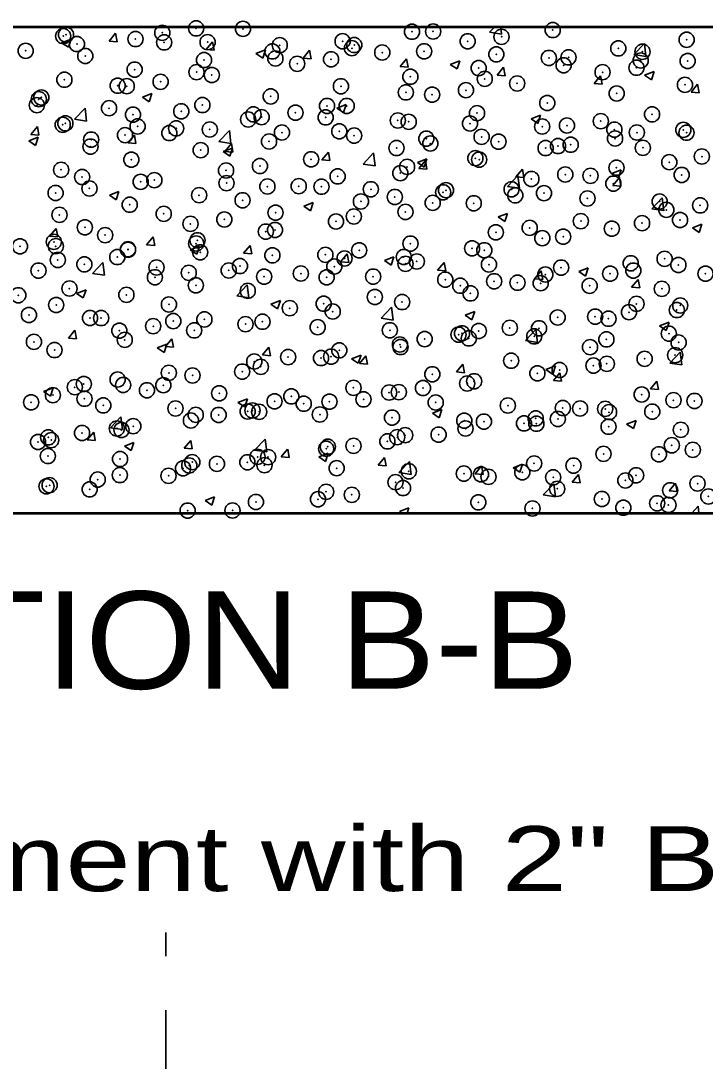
# Model space of a CAD drawing. Extents: x 14 to 49.3, y 28 to 50.
# Drawn here: x 21.16 to 22.425, y 46.258 to 48.18 of the extents above; entities that cross this region are included whole.
import ezdxf

# ---------------------------------------------------------------- set-up
doc = ezdxf.new("R2010")
doc.units = 0
doc.header["$LTSCALE"] = 0.056
doc.header["$PDMODE"] = 32
doc.header["$PDSIZE"] = 0.028
doc.linetypes.add('LONG_DASH_SHORT_DASH', pattern=[9.9, 6, -1.2, 1.5, -1.2])
for name, color, linetype, lineweight in [('1', 7, 'Continuous', 35), ('3', 7, 'Continuous', 13), ('7', 7, 'LONG_DASH_SHORT_DASH', 35)]:
    doc.layers.add(name, color=color, linetype=linetype, lineweight=lineweight)

msp = doc.modelspace()

# ---------------------------------------------------------------- linework, layer by layer
at = {"layer": '1'}
for p, q in [((22.02617, 48.15917), (22.03525, 48.16867)), ((22.04842, 48.15575), (22.04692, 48.16867)), ((21.23508, 48.13975), (21.25258, 48.1465)), ((21.2475, 48.13142), (21.25258, 48.1465)), ((21.32283, 48.14275), (21.33492, 48.15708)), ((21.32283, 48.14275), (21.33775, 48.14142)), ((21.33775, 48.14142), (21.33492, 48.15708)), ((21.50217, 48.127), (21.51417, 48.14142)), ((21.51708, 48.12575), (21.51425, 48.14142)), ((22.02617, 48.15917), (22.04833, 48.15575)), ((21.23508, 48.13975), (21.2475, 48.13142)), ((21.50217, 48.127), (21.51708, 48.12575)), ((21.59433, 48.11975), (21.61183, 48.1265)), ((21.60683, 48.11133), (21.61183, 48.1265)), ((21.68142, 48.11133), (21.6935, 48.12567)), ((21.69642, 48.11), (21.6935, 48.12567)), ((22.29292, 48.11783), (22.31242, 48.13808)), ((22.31517, 48.11433), (22.31242, 48.13808)), ((21.59433, 48.11975), (21.60675, 48.11142)), ((21.68142, 48.11133), (21.69642, 48.11)), ((21.86075, 48.09567), (21.87283, 48.11)), ((21.87575, 48.09433), (21.87283, 48.11)), ((21.95367, 48.09975), (21.97117, 48.1065)), ((21.96608, 48.09133), (21.97117, 48.10642)), ((22.29292, 48.11783), (22.31517, 48.11433)), ((21.86075, 48.09567), (21.87575, 48.09433)), ((21.95367, 48.09975), (21.96608, 48.09133)), ((22.04008, 48.08), (22.05217, 48.09433)), ((22.05508, 48.07867), (22.05217, 48.09433)), ((22.31292, 48.07975), (22.33042, 48.08642)), ((22.32533, 48.07133), (22.33042, 48.08642)), ((22.04008, 48.08), (22.055, 48.07867)), ((22.21942, 48.06425), (22.23142, 48.07867)), ((22.21942, 48.06425), (22.23433, 48.063)), ((22.23433, 48.063), (22.2315, 48.07867)), ((22.31292, 48.07975), (22.32533, 48.07133)), ((21.38433, 48.03917), (21.40183, 48.04583)), ((21.39675, 48.03075), (21.40183, 48.04583)), ((22.39875, 48.04858), (22.41075, 48.06292)), ((22.39875, 48.04858), (22.41367, 48.04725)), ((22.41367, 48.04725), (22.41075, 48.06292)), ((21.38433, 48.03917), (21.39675, 48.03075)), ((21.74358, 48.01908), (21.76108, 48.02583)), ((21.756, 48.01075), (21.76108, 48.02583)), ((21.25883, 47.99842), (21.27833, 48.01875)), ((21.28108, 47.995), (21.27833, 48.01875)), ((21.74358, 48.01908), (21.756, 48.01075)), ((22.10283, 47.99908), (22.12033, 48.00583)), ((22.11533, 47.99067), (22.12042, 48.00583)), ((21.25883, 47.99842), (21.28108, 47.995)), ((22.10283, 47.99908), (22.11533, 47.99067)), ((21.17817, 47.97033), (21.19025, 47.98475)), ((21.17817, 47.97033), (21.19317, 47.96908)), ((21.19317, 47.96908), (21.19025, 47.98475)), ((21.3575, 47.95467), (21.36958, 47.969)), ((21.3725, 47.95333), (21.36958, 47.969)), ((21.52567, 47.95708), (21.54517, 47.97733)), ((21.54792, 47.95358), (21.54517, 47.97733)), ((21.17425, 47.9585), (21.19175, 47.96525)), ((21.17425, 47.9585), (21.18667, 47.95008)), ((21.18667, 47.95008), (21.19175, 47.96525)), ((21.3575, 47.95467), (21.37242, 47.95333)), ((21.52567, 47.95708), (21.54792, 47.95358)), ((21.52567, 47.95708), (21.54792, 47.95358)), ((21.53683, 47.939), (21.54892, 47.95333)), ((21.55175, 47.93767), (21.54892, 47.95333)), ((21.5335, 47.9385), (21.551, 47.94517)), ((21.5335, 47.9385), (21.546, 47.93008)), ((21.53683, 47.939), (21.55175, 47.93767)), ((21.546, 47.93008), (21.55108, 47.94517)), ((21.71617, 47.92333), (21.72817, 47.93767)), ((21.73108, 47.922), (21.72825, 47.93767)), ((21.7925, 47.91567), (21.81192, 47.936)), ((21.81475, 47.91225), (21.81192, 47.93592)), ((21.71617, 47.92333), (21.73108, 47.922)), ((21.7925, 47.91567), (21.81467, 47.91225)), ((21.89283, 47.91842), (21.91033, 47.92517)), ((21.89283, 47.91842), (21.90525, 47.91008)), ((21.8955, 47.90758), (21.9075, 47.922)), ((21.90525, 47.91008), (21.91033, 47.92517)), ((21.91042, 47.90633), (21.9075, 47.922)), ((21.8955, 47.90758), (21.91042, 47.90633)), ((22.05925, 47.87425), (22.07875, 47.89458)), ((22.07475, 47.89192), (22.08683, 47.90625)), ((22.07475, 47.89192), (22.08975, 47.89058)), ((22.0815, 47.87083), (22.07875, 47.89458)), ((22.08975, 47.89058), (22.08683, 47.90625)), ((22.25208, 47.89842), (22.26958, 47.90517)), ((22.25208, 47.89842), (22.2645, 47.89008)), ((22.25408, 47.87625), (22.26617, 47.89058)), ((22.2645, 47.89), (22.26958, 47.90517)), ((22.26908, 47.87492), (22.26617, 47.89058)), ((22.05925, 47.87425), (22.0815, 47.87083)), ((22.25408, 47.87625), (22.269, 47.87492)), ((21.3235, 47.85783), (21.341, 47.86458)), ((21.3235, 47.85783), (21.33592, 47.84942)), ((21.33592, 47.84942), (21.341, 47.86458)), ((22.32608, 47.83292), (22.34558, 47.85317)), ((22.34833, 47.82942), (22.34558, 47.85317)), ((21.68275, 47.83783), (21.70025, 47.8445)), ((21.68275, 47.83783), (21.69517, 47.82942)), ((21.69517, 47.82942), (21.70025, 47.8445)), ((22.32608, 47.83292), (22.34833, 47.8295)), ((22.042, 47.81783), (22.0595, 47.8245)), ((22.042, 47.81783), (22.0545, 47.80942)), ((22.0545, 47.80942), (22.05958, 47.8245)), ((21.21292, 47.78233), (21.22492, 47.79667)), ((21.22783, 47.781), (21.22492, 47.79667)), ((22.40133, 47.79775), (22.41883, 47.8045)), ((22.40133, 47.79775), (22.41375, 47.78942)), ((22.41375, 47.78942), (22.41883, 47.8045)), ((21.21292, 47.78233), (21.22783, 47.781)), ((21.39217, 47.76658), (21.40425, 47.781)), ((21.40717, 47.76533), (21.40425, 47.781)), ((21.39217, 47.76658), (21.40717, 47.76533)), ((21.47267, 47.75717), (21.49017, 47.76392)), ((21.47267, 47.75717), (21.48517, 47.74883)), ((21.48517, 47.74883), (21.49025, 47.76392)), ((21.5715, 47.75092), (21.58358, 47.76533)), ((21.5865, 47.74958), (21.58358, 47.76533)), ((21.5715, 47.75092), (21.5865, 47.74967)), ((21.75083, 47.73525), (21.76292, 47.74958)), ((21.76575, 47.73392), (21.76292, 47.74958)), ((21.832, 47.73717), (21.8495, 47.74392)), ((21.832, 47.73717), (21.84442, 47.72875)), ((21.84442, 47.72875), (21.8495, 47.74392)), ((21.292, 47.7135), (21.3115, 47.73383)), ((21.31425, 47.71008), (21.3115, 47.73383)), ((21.75083, 47.73525), (21.76575, 47.73392)), ((21.93017, 47.71958), (21.94217, 47.73392)), ((21.93017, 47.71958), (21.94508, 47.71825)), ((21.94508, 47.71825), (21.94225, 47.73392)), ((22.1095, 47.70383), (22.1215, 47.71825)), ((22.12442, 47.70258), (22.1215, 47.71825)), ((22.19125, 47.71717), (22.20875, 47.72383)), ((22.20375, 47.70875), (22.20875, 47.72383)), ((21.292, 47.7135), (21.31425, 47.71008)), ((22.1095, 47.70383), (22.12442, 47.70258)), ((22.19125, 47.71717), (22.20367, 47.70875)), ((22.28875, 47.68817), (22.30083, 47.70258)), ((22.30375, 47.68683), (22.30083, 47.7025)), ((21.26267, 47.67658), (21.28017, 47.68325)), ((21.27508, 47.66817), (21.28017, 47.68325)), ((21.55883, 47.67217), (21.57825, 47.69242)), ((21.58108, 47.66867), (21.57825, 47.69242)), ((22.28875, 47.68817), (22.30375, 47.68683)), ((21.26267, 47.67658), (21.27508, 47.66817)), ((21.55883, 47.67217), (21.581, 47.66867)), ((21.62192, 47.6565), (21.63942, 47.66325)), ((21.63433, 47.64817), (21.63942, 47.66325)), ((21.62192, 47.6565), (21.63433, 47.64817)), ((21.82558, 47.63075), (21.84508, 47.65108)), ((21.84783, 47.62733), (21.84508, 47.65108)), ((21.98117, 47.6365), (21.99875, 47.64325)), ((21.99367, 47.62808), (21.99875, 47.64325)), ((21.82558, 47.63075), (21.84783, 47.62733)), ((21.98117, 47.6365), (21.99367, 47.62808)), ((22.3405, 47.6165), (22.358, 47.62325)), ((22.35292, 47.60808), (22.358, 47.62317)), ((21.24758, 47.59425), (21.25967, 47.60867)), ((21.2625, 47.59292), (21.25967, 47.60858)), ((22.09242, 47.58942), (22.11192, 47.60967)), ((22.11467, 47.58592), (22.11192, 47.60967)), ((22.3405, 47.6165), (22.35292, 47.60808)), ((21.24758, 47.59425), (21.2625, 47.59292)), ((21.42692, 47.57858), (21.43892, 47.59292)), ((21.44183, 47.57725), (21.43892, 47.59292)), ((21.44183, 47.57725), (21.43892, 47.59292)), ((22.09242, 47.58942), (22.11467, 47.58592)), ((21.41183, 47.57592), (21.42933, 47.58258)), ((21.41183, 47.57592), (21.42433, 47.5675)), ((21.42433, 47.5675), (21.42942, 47.58258)), ((21.42692, 47.57858), (21.44183, 47.57725)), ((21.60617, 47.56292), (21.61825, 47.57725)), ((21.62117, 47.56158), (21.61825, 47.57725)), ((22.35925, 47.548), (22.37867, 47.56833)), ((22.3815, 47.54458), (22.37875, 47.56825)), ((21.60617, 47.56292), (21.62117, 47.56158)), ((21.77117, 47.55592), (21.78867, 47.56258)), ((21.77117, 47.55592), (21.78358, 47.5475)), ((21.78358, 47.5475), (21.78867, 47.56258)), ((21.7855, 47.54717), (21.79758, 47.56158)), ((21.7855, 47.54717), (21.8005, 47.54592)), ((21.8005, 47.54592), (21.79758, 47.56158)), ((21.96483, 47.5315), (21.97692, 47.54583)), ((21.97983, 47.53017), (21.97692, 47.54583)), ((22.35925, 47.548), (22.3815, 47.54458)), ((21.96483, 47.5315), (21.97975, 47.53017)), ((22.13042, 47.53583), (22.14792, 47.54258)), ((22.13042, 47.53583), (22.14283, 47.5275)), ((22.14292, 47.5275), (22.14792, 47.54258)), ((22.14417, 47.51583), (22.15617, 47.53017)), ((22.15908, 47.5145), (22.15625, 47.53017)), ((22.14417, 47.51583), (22.15908, 47.5145)), ((22.3235, 47.50017), (22.3355, 47.5145)), ((22.33842, 47.49883), (22.3355, 47.5145)), ((21.20183, 47.49525), (21.21933, 47.502)), ((21.20183, 47.49525), (21.21425, 47.48692)), ((21.21425, 47.48692), (21.21933, 47.502)), ((22.3235, 47.50017), (22.33842, 47.49883)), ((21.56108, 47.47525), (21.57858, 47.482)), ((21.56108, 47.47525), (21.5735, 47.46683)), ((21.57358, 47.46683), (21.57858, 47.482)), ((21.32517, 47.42858), (21.34458, 47.44892)), ((21.34742, 47.42517), (21.34458, 47.44892)), ((21.92042, 47.45525), (21.93792, 47.46192)), ((21.92042, 47.45525), (21.93283, 47.44683)), ((21.93283, 47.44683), (21.93792, 47.46192)), ((22.27967, 47.43517), (22.29717, 47.44192)), ((22.27967, 47.43517), (22.29208, 47.42683)), ((22.29208, 47.42683), (22.29717, 47.44192)), ((21.28225, 47.40625), (21.29433, 47.42058)), ((21.29725, 47.40492), (21.29433, 47.42058)), ((21.32517, 47.42858), (21.34733, 47.42517)), ((21.28225, 47.40625), (21.29717, 47.40492)), ((21.351, 47.39458), (21.36858, 47.40133)), ((21.351, 47.39458), (21.3635, 47.38625)), ((21.3635, 47.38625), (21.36858, 47.40133)), ((21.46158, 47.3905), (21.47367, 47.40492)), ((21.46158, 47.3905), (21.4765, 47.38925)), ((21.4765, 47.38925), (21.47367, 47.40492)), ((21.59192, 47.38725), (21.61142, 47.4075)), ((21.61417, 47.38375), (21.61142, 47.4075)), ((21.59192, 47.38725), (21.61417, 47.38375)), ((21.64092, 47.37483), (21.65292, 47.38917)), ((21.64092, 47.37483), (21.65583, 47.3735)), ((21.65583, 47.3735), (21.653, 47.38917)), ((21.71033, 47.37458), (21.72783, 47.38133)), ((21.71033, 47.37458), (21.72275, 47.36617)), ((21.71033, 47.37458), (21.72275, 47.36617)), ((21.72275, 47.36617), (21.72783, 47.38133)), ((21.82017, 47.35917), (21.83225, 47.3735)), ((21.83517, 47.35783), (21.83225, 47.3735)), ((21.82017, 47.35917), (21.83517, 47.35783)), ((21.85875, 47.34583), (21.87825, 47.36617)), ((21.881, 47.34242), (21.87825, 47.36617)), ((21.9995, 47.3435), (22.01158, 47.35783)), ((22.0145, 47.34217), (22.01158, 47.35783)), ((22.06958, 47.35458), (22.08708, 47.36125)), ((22.06958, 47.35458), (22.082, 47.34617)), ((22.08208, 47.34617), (22.08708, 47.36125)), ((21.85875, 47.34583), (21.881, 47.34242)), ((21.9995, 47.3435), (22.0145, 47.34217)), ((22.17883, 47.32775), (22.19092, 47.34217)), ((22.19383, 47.3265), (22.19092, 47.34217)), ((22.12558, 47.3045), (22.145, 47.32475)), ((22.14783, 47.301), (22.14508, 47.32475)), ((22.17883, 47.32775), (22.19375, 47.3265)), ((22.35817, 47.31208), (22.37017, 47.32642)), ((22.37308, 47.31075), (22.37025, 47.32642)), ((21.50025, 47.294), (21.51775, 47.30067)), ((21.51275, 47.28558), (21.51775, 47.30067)), ((22.12558, 47.3045), (22.14783, 47.301)), ((22.35817, 47.31208), (22.37308, 47.31075)), ((21.50025, 47.294), (21.51267, 47.28558)), ((21.85958, 47.27392), (21.87708, 47.28067)), ((21.87383, 47.271), (21.87708, 47.28067)), ((22.4, 47.271), (22.41183, 47.28342)), ((22.41333, 47.271), (22.41183, 47.28342)), ((21.85958, 47.27392), (21.86383, 47.271))]:
    msp.add_line(p, q, dxfattribs=at)
at = {"layer": '1', "lineweight": 53}
for points in [[(22.63958, 47.92558), (22.63958, 48.05642), (22.63067, 48.12192), (22.57725, 48.16867), (20.43842, 48.16867), (20.39383, 48.11258), (20.38492, 48.02842)], [(18.87883, 47.271), (23.89617, 47.271), (23.90508, 47.29908), (23.88725, 47.34583), (23.86942, 47.39258), (23.89617, 47.43933), (23.92292, 47.47675), (23.914, 47.51417), (23.87833, 47.57958), (23.8605, 47.63567), (23.89617, 47.66375), (23.914, 47.77592), (23.914, 47.79467)]]:
    msp.add_lwpolyline(points, dxfattribs=at)
at = {"layer": '1'}
for p in [(21.48375, 48.16617), (21.57033, 48.16525), (21.238, 48.152), (21.24317, 48.15458), (21.3715, 48.14642), (21.42117, 48.158), (21.88283, 48.16), (21.92183, 48.16042), (22.04833, 48.15058), (22.143, 48.16308), (21.26333, 48.13717), (21.42458, 48.14025), (21.50492, 48.14075), (21.63833, 48.13508), (21.7545, 48.14242), (21.77183, 48.1295), (21.77608, 48.13542), (21.98575, 48.14233), (22.26425, 48.12917), (22.39058, 48.14517), (21.16858, 48.12475), (21.27875, 48.11525), (21.49833, 48.10767), (21.62467, 48.12367), (21.63025, 48.11042), (21.73317, 48.10908), (21.82783, 48.12158), (21.90525, 48.12383), (22.03875, 48.11817), (22.13592, 48.11158), (22.17217, 48.11258), (22.30567, 48.10692), (22.30892, 48.123), (21.37, 48.09008), (21.67058, 48.10083), (22.00608, 48.09283), (22.16317, 48.098), (22.29775, 48.0935), (22.39242, 48.10592), (21.24017, 48.07133), (21.4845, 48.08533), (21.51267, 48.08008), (21.87983, 48.07683), (22.01733, 48.07292), (22.23517, 48.08525), (21.33867, 48.06033), (21.35542, 48.05933), (21.418, 48.06758), (21.75142, 48.05925), (21.98258, 48.052), (22.07725, 48.06442), (22.3875, 48.06192), (21.19283, 48.03533), (21.1975, 48.03858), (21.62158, 48.0405), (21.8715, 48.04792), (21.92, 48.04375), (22.26125, 48.04592), (21.18933, 48.02425), (21.32275, 48.01867), (21.45625, 48.013), (21.49533, 48.0245), (21.72575, 48.02292), (21.76208, 48.02292), (22.13292, 48.02833), (21.367, 48.00683), (21.57992, 47.99783), (21.58967, 48.00733), (21.60483, 48.00225), (21.66742, 48.0105), (21.72317, 48.00175), (21.85658, 47.99608), (21.87675, 47.99358), (22.00308, 48.00958), (22.23192, 47.99483), (22.32667, 48.00733), (21.23708, 47.98808), (21.242, 47.99075), (21.3755, 47.98508), (21.43417, 47.97283), (21.44692, 47.9815), (21.50892, 47.97942), (21.64242, 47.97383), (21.74842, 47.976), (21.99008, 47.99042), (22.1235, 47.98483), (22.16933, 47.98667), (22.257, 47.97917), (22.29858, 47.97383), (22.3845, 47.97875), (22.39042, 47.9735), (21.28967, 47.96075), (21.35225, 47.969), (21.61858, 47.95725), (21.77583, 47.96817), (21.90933, 47.9625), (21.91675, 47.95342), (22.0115, 47.96583), (22.04275, 47.95692), (22.25825, 47.96275), (21.28833, 47.94783), (21.49225, 47.94125), (21.85417, 47.94517), (22.12983, 47.94508), (22.15283, 47.94883), (22.17625, 47.95125), (22.30967, 47.94558), (21.36392, 47.92367), (21.69633, 47.92433), (22, 47.92633), (22.007, 47.92375), (22.3585, 47.91892), (22.41875, 47.9295), (21.23408, 47.90492), (21.53908, 47.90367), (21.60167, 47.91192), (21.86125, 47.89875), (21.87375, 47.91033), (22.16617, 47.89625), (22.26083, 47.90875), (22.38142, 47.8955), (21.273, 47.89158), (21.38117, 47.88283), (21.4065, 47.88592), (21.53992, 47.88033), (21.74533, 47.89275), (22.10358, 47.888), (22.21275, 47.89392), (22.25517, 47.8795), (21.22392, 47.86217), (21.2865, 47.87042), (21.48925, 47.858), (21.6155, 47.874), (21.67342, 47.87467), (21.71542, 47.87375), (21.80683, 47.869), (21.94033, 47.86342), (21.94567, 47.86725), (22.06692, 47.86892), (22.07375, 47.85775), (22.12683, 47.86192), (21.36092, 47.84042), (21.56958, 47.84867), (21.78842, 47.8465), (21.851, 47.85475), (21.92108, 47.84383), (21.997, 47.84317), (22.20725, 47.85208), (22.34067, 47.8465), (22.41558, 47.83917), (21.231, 47.82167), (21.42383, 47.82367), (21.63058, 47.82575), (21.77533, 47.81883), (21.87067, 47.82717), (22.353, 47.83092), (21.47325, 47.80508), (21.53583, 47.81325), (21.74233, 47.8095), (22.19508, 47.81017), (22.30817, 47.80642), (22.37842, 47.81225), (21.278, 47.79867), (21.31542, 47.78425), (21.6125, 47.79083), (21.6295, 47.79383), (22.03783, 47.78942), (22.10042, 47.79767), (22.16242, 47.78142), (22.25217, 47.79625), (21.15808, 47.76358), (21.22075, 47.77183), (21.22433, 47.76383), (21.48375, 47.76875), (21.48617, 47.77475), (21.87992, 47.76867), (22.12375, 47.77867), (21.33792, 47.74375), (21.35783, 47.75817), (21.35783, 47.75717), (21.49125, 47.75258), (21.62475, 47.74692), (21.72267, 47.74792), (21.78525, 47.75617), (21.86767, 47.74392), (21.99392, 47.75992), (22.01658, 47.75633), (21.228, 47.73842), (21.27708, 47.73025), (21.4105, 47.72458), (21.56475, 47.72717), (21.73925, 47.72633), (21.75817, 47.74125), (21.87083, 47.73133), (21.89167, 47.73567), (22.02508, 47.73), (22.15858, 47.72433), (22.28725, 47.73233), (22.34983, 47.74058), (22.37533, 47.72908), (21.19217, 47.71875), (21.4075, 47.70642), (21.47008, 47.71467), (21.544, 47.719), (21.60942, 47.70758), (21.67742, 47.71333), (21.725, 47.70633), (21.81092, 47.70767), (22.12933, 47.7115), (22.24908, 47.71308), (22.292, 47.71875), (22.42542, 47.71308), (21.24958, 47.68567), (21.48317, 47.69158), (21.94433, 47.70208), (21.97208, 47.69083), (22.03467, 47.69908), (22.07783, 47.69642), (22.12075, 47.69542), (22.21125, 47.69075), (22.34475, 47.68517), (21.15492, 47.67317), (21.35483, 47.674), (21.57917, 47.68133), (21.81417, 47.67), (21.99092, 47.67667), (21.225, 47.65525), (21.43342, 47.65625), (21.65692, 47.64933), (21.7195, 47.65758), (21.86458, 47.66067), (22.29783, 47.65725), (22.37233, 47.64583), (22.37875, 47.65442), (21.17458, 47.63675), (21.28758, 47.63125), (21.30808, 47.63108), (21.499, 47.62858), (21.73625, 47.64308), (22.15208, 47.63225), (22.22142, 47.63375), (22.24608, 47.62983), (22.284, 47.64192), (21.34175, 47.60783), (21.40433, 47.61608), (21.4415, 47.6255), (21.48017, 47.60833), (21.575, 47.61983), (21.60642, 47.62433), (21.70842, 47.61417), (21.84192, 47.60858), (22.00625, 47.60717), (22.06358, 47.61292), (22.11767, 47.61225), (21.35175, 47.59075), (21.90625, 47.59225), (21.96883, 47.6005), (21.97533, 47.60292), (21.98783, 47.5935), (22.10883, 47.59725), (22.24225, 47.59167), (22.35775, 47.60233), (21.18383, 47.58708), (21.22192, 47.572), (21.74842, 47.57142), (21.8605, 47.58217), (21.86158, 47.5775), (22.212, 47.57733), (22.37575, 47.586), (21.59117, 47.55075), (21.65375, 47.559), (21.71467, 47.55717), (21.73325, 47.55983), (22.06617, 47.55233), (22.31292, 47.55583), (22.36925, 47.56258), (21.56892, 47.53217), (21.60333, 47.54108), (22.15567, 47.53508), (22.21825, 47.54333), (22.243, 47.54658), (21.33858, 47.5175), (21.43325, 47.52992), (21.47708, 47.52508), (21.92042, 47.52725), (21.99775, 47.51433), (22.11467, 47.529), (21.25942, 47.50333), (21.276, 47.50925), (21.34875, 47.5075), (21.39283, 47.49775), (21.42308, 47.50708), (21.52633, 47.49208), (21.77458, 47.50225), (21.8405, 47.49358), (21.8585, 47.49425), (21.90308, 47.50183), (21.98483, 47.51025), (21.17867, 47.47542), (21.21892, 47.48875), (21.27725, 47.48208), (21.62875, 47.47725), (21.65975, 47.48642), (21.68267, 47.47283), (21.73017, 47.47667), (21.79325, 47.48083), (21.92667, 47.47517), (22.30742, 47.48983), (22.36625, 47.47942), (22.40508, 47.478), (21.31208, 47.46975), (21.44558, 47.46417), (21.579, 47.4585), (21.58792, 47.46033), (21.60033, 47.45792), (22.06008, 47.4695), (22.16167, 47.46483), (22.19358, 47.46392), (22.24, 47.46342), (22.24717, 47.45725), (22.327, 47.45825), (21.47408, 47.44192), (21.483, 47.45225), (21.52533, 47.45217), (21.7125, 47.45283), (21.84592, 47.44725), (21.97942, 47.44158), (22.01583, 47.43983), (22.08992, 47.4365), (22.11158, 47.44575), (22.11283, 47.43592), (22.1525, 47.44475), (21.27283, 47.41883), (21.33717, 47.42717), (21.34567, 47.42433), (21.3675, 47.43133), (21.932, 47.41575), (21.98175, 47.427), (22.24625, 47.43033), (22.37975, 47.42467), (21.19142, 47.40217), (21.21025, 47.41067), (21.21583, 47.40558), (21.83733, 47.40325), (21.8555, 47.411), (21.87008, 47.41475), (22.36317, 47.39617), (21.72425, 47.38975), (21.72717, 47.39342), (21.77475, 47.395), (22.23692, 47.38017), (22.33933, 47.37942), (22.40192, 47.38767), (21.20967, 47.37625), (21.34308, 47.37067), (21.471, 47.35867), (21.47658, 47.365), (21.52217, 47.36175), (21.5785, 47.36475), (21.59725, 47.37467), (21.61, 47.35933), (21.61683, 47.37425), (22.10858, 47.36258), (22.18142, 47.35858), (21.34267, 47.34108), (21.43267, 47.33967), (21.45958, 47.3535), (21.7435, 47.35375), (21.87692, 47.34808), (21.97875, 47.34383), (22.01042, 47.34242), (22.08675, 47.34617), (22.29717, 47.34067), (21.207, 47.32025), (21.21283, 47.32233), (21.30175, 47.33275), (21.85242, 47.32783), (22.02417, 47.33792), (22.14383, 47.33683), (22.27733, 47.33117), (22.41075, 47.3255), (21.28692, 47.31467), (21.72408, 47.31017), (21.77158, 47.30467), (21.86625, 47.31708), (22.15133, 47.31567), (22.36017, 47.31292), (22.43083, 47.3015), (21.59425, 47.29142), (21.709, 47.29642), (22.0055, 47.29067), (22.23392, 47.29692), (22.2735, 47.28075), (22.33608, 47.289), (22.357, 47.28583), (21.468, 47.27542), (21.55108, 47.27567), (22.1055, 47.27933)]:
    msp.add_point(p, dxfattribs=at)
at = {"layer": '7'}
msp.add_line((21.42758, 42.2005), (21.42758, 46.49608), dxfattribs=at)

# ---------------------------------------------------------------- texts
at = {"layer": '3'}
for s, height, width, p in [('SECTION B-B', 0.18, 1.1, (20.49892, 46.94625)), ('Concrete Transition Pavement with 2" Bituminous Overlay', 0.12, 1.35, (18.61742, 46.5725))]:
    msp.add_text(s, height=height, dxfattribs=dict(at, width=width)).set_placement(p)

doc.saveas('drawing.dxf')
